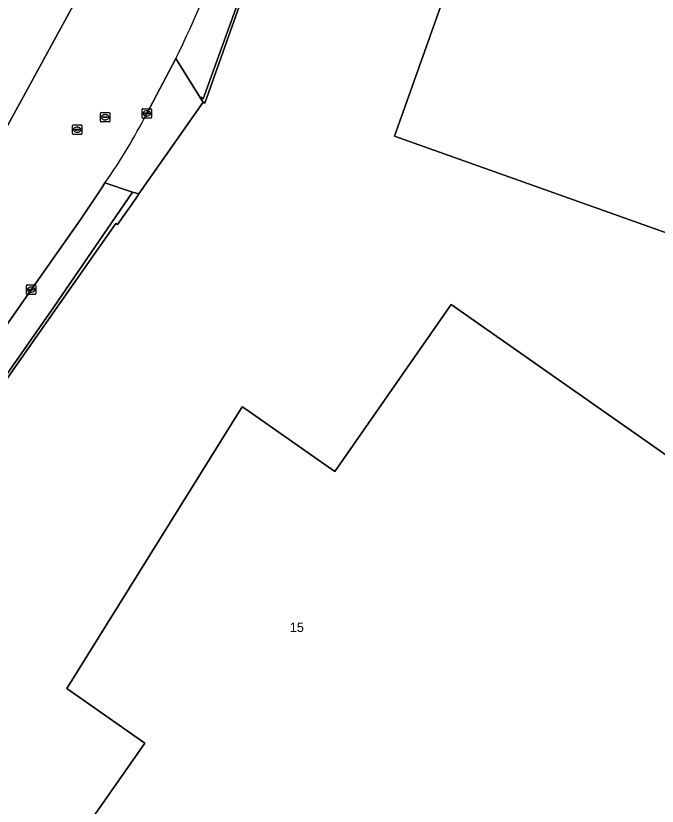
# Model space of a CAD drawing. Extents: x 155018 to 156648, y 383979 to 385733.
# Drawn here: x 155656.4 to 155724.8, y 384791.5 to 384875.8 of the extents above; entities that cross this region are included whole.
import ezdxf

# ---------------------------------------------------------------- set-up
doc = ezdxf.new("R2010")
doc.units = 0
for name, color, linetype in [('IMGEO_Erf', 7, 'Continuous'), ('IMGEO_Groenvoorziening', 7, 'Continuous'), ('IMGEO_Hek', 7, 'Continuous'), ('IMGEO_Kolk', 7, 'Continuous'), ('IMGEO_Pand', 7, 'Continuous'), ('IMGEO_Pand_nummerreeks', 7, 'Continuous'), ('IMGEO_Rijbaan_lokaal_gesloten', 7, 'Continuous'), ('IMGEO_Rijbaan_lokaal_open', 7, 'Continuous'), ('IMGEO_Rioolput', 7, 'Continuous'), ('IMGEO_Voetpad_open', 7, 'Continuous')]:
    doc.layers.add(name, color=color, linetype=linetype)

msp = doc.modelspace()

# ---------------------------------------------------------------- linework, layer by layer
at = {"layer": 'IMGEO_Erf'}
for points in [[(155819.22, 384821.585), (155773.299, 384837.894), (155771.729, 384833.45), (155765.854, 384835.53), (155767.438, 384839.985), (155767.038, 384840.129), (155766.348, 384838.189), (155696.765, 384862.93), (155727.468, 384949.235), (155728.915, 384948.717), (155740.174, 384980.395), (155746.303, 384997.642), (155748.837, 385004.772), (155747.33, 385005.279), (155749.138, 385010.33), (155750.623, 385009.797), (155753.183, 385017.001), (155762.359, 385042.817)], [(155730.975, 385018.536), (155724.402, 385000), (155719.139, 384985.171), (155718.598, 384983.687), (155716.009, 384976.585), (155715.7, 384975.738), (155702.844, 384939.771), (155702.172, 384937.868), (155696.786, 384922.628), (155696.12, 384920.743), (155684.958, 384889.381), (155684.425, 384889.57), (155682.806, 384885.06), (155682.424, 384883.902), (155681.972, 384882.563), (155681.138, 384880.234), (155681.15, 384879.519), (155676.547, 384866.454), (155676.35, 384866.575), (155669.497, 384856.797), (155669.212, 384856.331), (155667.198, 384853.508), (155667.02, 384853.625), (155588.106, 384741.158)], [(155662.832, 384787.785), (155670.123, 384798.196), (155661.809, 384804.018), (155680.521, 384834.071), (155680.893, 384833.825), (155690.4, 384827.184), (155702.826, 384844.99), (155791.889, 384782.576)]]:
    msp.add_lwpolyline(points, dxfattribs=at)
at = {"layer": 'IMGEO_Groenvoorziening'}
for points in [[(155681.15, 384879.519), (155681.138, 384880.234), (155676.369, 384866.915), (155676.09, 384867.098), (155676.052, 384866.993), (155676.35, 384866.575), (155676.547, 384866.454)], [(155667.02, 384853.625), (155667.198, 384853.508), (155669.212, 384856.331), (155669.497, 384856.797), (155668.817, 384856.954), (155660.389, 384844.659), (155636.862, 384811.074), (155608.808, 384771.107), (155594.019, 384750), (155586.655, 384739.49), (155582.342, 384733.152), (155582.316, 384732.95), (155582.416, 384732.885), (155582.631, 384733.19), (155586.789, 384739.087), (155588.217, 384741.112), (155588.106, 384741.158)]]:
    msp.add_lwpolyline(points, close=True, dxfattribs=at)
at = {"layer": 'IMGEO_Hek'}
for points in [[(155681.15, 384879.519), (155676.547, 384866.454), (155676.35, 384866.575)], [(155676.35, 384866.575), (155669.497, 384856.797)], [(155669.497, 384856.797), (155669.212, 384856.331)], [(155586.789, 384739.087), (155588.217, 384741.112), (155588.106, 384741.158), (155667.02, 384853.625), (155667.198, 384853.508), (155669.212, 384856.331)]]:
    msp.add_lwpolyline(points, dxfattribs=at)
at = {"layer": 'IMGEO_Kolk'}
for p, q in [((155669.836, 384864.948), (155669.836, 384865.8)), ((155669.911, 384865.874), (155670.763, 384865.874)), ((155670.837, 384865.8), (155670.837, 384864.948)), ((155670.095, 384865.368), (155670.095, 384865.38)), ((155670.533, 384865.331), (155670.135, 384865.331)), ((155670.138, 384865.417), (155670.536, 384865.417)), ((155670.347, 384865.094), (155670.322, 384865.094)), ((155670.324, 384865.654), (155670.349, 384865.654)), ((155670.579, 384865.38), (155670.579, 384865.368)), ((155670.763, 384864.874), (155669.911, 384864.874)), ((155657.498, 384846.145), (155657.498, 384846.997)), ((155657.573, 384847.071), (155658.425, 384847.071)), ((155657.757, 384846.565), (155657.757, 384846.577)), ((155658.195, 384846.528), (155657.797, 384846.528)), ((155657.8, 384846.614), (155658.198, 384846.614)), ((155657.986, 384846.851), (155658.011, 384846.851)), ((155658.241, 384846.577), (155658.241, 384846.565)), ((155658.499, 384846.997), (155658.499, 384846.145)), ((155658.425, 384846.071), (155657.573, 384846.071)), ((155658.009, 384846.291), (155657.984, 384846.291))]:
    msp.add_line(p, q, dxfattribs=at)
for points in [[(155669.836, 384864.948), (155669.836, 384865.8)], [(155669.911, 384865.874), (155670.763, 384865.874)], [(155670.837, 384865.8), (155670.837, 384864.948)], [(155670.763, 384864.874), (155669.911, 384864.874)], [(155657.498, 384846.145), (155657.498, 384846.997)], [(155657.573, 384847.071), (155658.425, 384847.071)], [(155658.499, 384846.997), (155658.499, 384846.145)], [(155658.425, 384846.071), (155657.573, 384846.071)]]:
    msp.add_lwpolyline(points, dxfattribs=at)
for centre, radius, start, end in [((155669.913, 384865.798), 0.0765, 91.55205, 178.44795), ((155669.913, 384865.798), 0.0765, 91.55205, 178.44795), ((155670.761, 384865.798), 0.0765, 1.55205, 88.44795), ((155670.761, 384865.798), 0.0765, 1.55205, 88.44795), ((155669.913, 384864.95), 0.0765, 181.55205, 268.44795), ((155669.913, 384864.95), 0.0765, 181.55205, 268.44795), ((155670.135, 384865.377), 0.0403, 85.87752, 175.75265), ((155670.132, 384865.367), 0.0366, 178.93798, 274.71019), ((155670.536, 384865.374), 0.043, 264.86636, 352.45326), ((155670.54, 384865.379), 0.0386, 1.73085, 96.63898), ((155670.761, 384864.95), 0.0765, 271.55205, 358.44795), ((155670.761, 384864.95), 0.0765, 271.55205, 358.44795), ((155657.575, 384846.995), 0.0765, 91.55205, 178.44795), ((155657.575, 384846.995), 0.0765, 91.55205, 178.44795), ((155657.797, 384846.574), 0.0403, 85.87752, 175.75265), ((155657.794, 384846.564), 0.0366, 178.93798, 274.71019), ((155658.198, 384846.571), 0.043, 264.86636, 352.45326), ((155658.202, 384846.576), 0.0386, 1.73085, 96.63898), ((155658.423, 384846.995), 0.0765, 1.55205, 88.44795), ((155658.423, 384846.995), 0.0765, 1.55205, 88.44795), ((155657.575, 384846.147), 0.0765, 181.55205, 268.44795), ((155657.575, 384846.147), 0.0765, 181.55205, 268.44795), ((155658.423, 384846.147), 0.0765, 271.55205, 358.44795), ((155658.423, 384846.147), 0.0765, 271.55205, 358.44795)]:
    msp.add_arc(centre, radius, start, end, dxfattribs=at)
for centre, major_axis, ratio, start_param, end_param in [((155670.323, 384865.374), (-0.387, 0.002), 0.722429, 4.712389, 7.853982), ((155670.348, 384865.374), (-0.39, 0.002), 0.717154, 1.570796, 4.712389), ((155657.985, 384846.571), (-0.387, 0.002), 0.722429, 4.712389, 7.853982), ((155658.01, 384846.571), (-0.39, 0.002), 0.717154, 1.570796, 4.712389)]:
    msp.add_ellipse(centre, major_axis=major_axis, ratio=ratio, start_param=start_param, end_param=end_param, dxfattribs=at)
at = {"layer": 'IMGEO_Pand'}
for points in [[(155828.255, 384911.336), (155796.179, 384922.734), (155808.139, 384956.274), (155787.494, 384963.57), (155797.027, 384990.446), (155809.649, 385026.028), (155762.359, 385042.817), (155753.183, 385017.001), (155750.623, 385009.797), (155749.138, 385010.33), (155747.33, 385005.279), (155748.837, 385004.772), (155746.303, 384997.642), (155740.174, 384980.395), (155728.915, 384948.717), (155727.468, 384949.235), (155696.765, 384862.93), (155766.348, 384838.189), (155767.038, 384840.129), (155767.438, 384839.985), (155765.854, 384835.53), (155771.729, 384833.45), (155773.299, 384837.894), (155819.22, 384821.585)], [(155791.889, 384782.576), (155702.826, 384844.99), (155690.4, 384827.184), (155680.893, 384833.825), (155680.521, 384834.071), (155661.809, 384804.018), (155670.123, 384798.196), (155662.832, 384787.785)]]:
    msp.add_lwpolyline(points, dxfattribs=at)
at = {"layer": 'IMGEO_Rijbaan_lokaal_gesloten'}
for points in [[(155654.873, 384862.94), (155662.924, 384877.712)], [(155662.924, 384877.712), (155654.873, 384862.94)], [(155670.338, 384865.374), (155673.443, 384871.217)], [(155557.839, 384704.064), (155557.967, 384704.242), (155558.339, 384703.973), (155565.165, 384713.55), (155573.586, 384725.999), (155578.096, 384732.463), (155583.356, 384740.042), (155586.289, 384744.214), (155590.343, 384750), (155608.173, 384775.45), (155620.847, 384793.568), (155634.39, 384812.919), (155647.778, 384831.987), (155658, 384846.57), (155663.285, 384854.104), (155665.547, 384857.446), (155665.874, 384857.967)]]:
    msp.add_lwpolyline(points, dxfattribs=at)
for centre, radius, start, end in [((155522.654, 384943.7), 167.306, 334.32678, 339.20632), ((155617.397, 384892.231), 59.364, 324.74661, 333.1009)]:
    msp.add_arc(centre, radius, start, end, dxfattribs=at)
at = {"layer": 'IMGEO_Rijbaan_lokaal_open'}
for points in [[(155676.35, 384866.575), (155676.052, 384866.993), (155673.443, 384871.217), (155670.338, 384865.374)], [(155665.874, 384857.967), (155668.817, 384856.954), (155669.497, 384856.797), (155676.35, 384866.575)]]:
    msp.add_lwpolyline(points, dxfattribs=at)
msp.add_arc((155617.397, 384892.231), 59.364, 324.74661, 333.1009, dxfattribs=at)
at = {"layer": 'IMGEO_Rioolput'}
for p, q in [((155665.382, 384864.54), (155665.382, 384865.392)), ((155665.457, 384865.466), (155666.309, 384865.466)), ((155665.641, 384864.96), (155665.641, 384864.972)), ((155665.684, 384865.009), (155666.082, 384865.009)), ((155665.87, 384865.246), (155665.895, 384865.246)), ((155666.125, 384864.972), (155666.125, 384864.96)), ((155666.383, 384865.392), (155666.383, 384864.54)), ((155662.497, 384864.139), (155663.349, 384864.139)), ((155666.309, 384864.466), (155665.457, 384864.466)), ((155666.079, 384864.923), (155665.681, 384864.923)), ((155665.893, 384864.686), (155665.868, 384864.686)), ((155662.422, 384863.213), (155662.422, 384864.065)), ((155662.681, 384863.633), (155662.681, 384863.645)), ((155663.119, 384863.596), (155662.721, 384863.596)), ((155662.724, 384863.682), (155663.122, 384863.682)), ((155662.933, 384863.359), (155662.908, 384863.359)), ((155662.91, 384863.919), (155662.935, 384863.919)), ((155663.165, 384863.645), (155663.165, 384863.633)), ((155663.423, 384864.065), (155663.423, 384863.213)), ((155663.349, 384863.139), (155662.497, 384863.139))]:
    msp.add_line(p, q, dxfattribs=at)
for points in [[(155665.382, 384864.54), (155665.382, 384865.392)], [(155665.457, 384865.466), (155666.309, 384865.466)], [(155666.383, 384865.392), (155666.383, 384864.54)], [(155662.497, 384864.139), (155663.349, 384864.139)], [(155666.309, 384864.466), (155665.457, 384864.466)], [(155662.422, 384863.213), (155662.422, 384864.065)], [(155663.423, 384864.065), (155663.423, 384863.213)], [(155663.349, 384863.139), (155662.497, 384863.139)]]:
    msp.add_lwpolyline(points, dxfattribs=at)
for centre, radius, start, end in [((155665.459, 384865.39), 0.0765, 91.55205, 178.44795), ((155665.459, 384865.39), 0.0765, 91.55205, 178.44795), ((155665.681, 384864.969), 0.0403, 85.87752, 175.75265), ((155665.678, 384864.959), 0.0366, 178.93798, 274.71019), ((155666.082, 384864.966), 0.043, 264.86636, 352.45326), ((155666.086, 384864.971), 0.0386, 1.73085, 96.63898), ((155666.307, 384865.39), 0.0765, 1.55205, 88.44795), ((155666.307, 384865.39), 0.0765, 1.55205, 88.44795), ((155662.499, 384864.063), 0.0765, 91.55205, 178.44795), ((155662.499, 384864.063), 0.0765, 91.55205, 178.44795), ((155663.347, 384864.063), 0.0765, 1.55205, 88.44795), ((155663.347, 384864.063), 0.0765, 1.55205, 88.44795), ((155665.459, 384864.542), 0.0765, 181.55205, 268.44795), ((155665.459, 384864.542), 0.0765, 181.55205, 268.44795), ((155666.307, 384864.542), 0.0765, 271.55205, 358.44795), ((155666.307, 384864.542), 0.0765, 271.55205, 358.44795), ((155662.721, 384863.642), 0.0403, 85.87752, 175.75265), ((155662.718, 384863.632), 0.0366, 178.93798, 274.71019), ((155663.122, 384863.639), 0.043, 264.86636, 352.45326), ((155663.126, 384863.644), 0.0386, 1.73085, 96.63898), ((155662.499, 384863.215), 0.0765, 181.55205, 268.44795), ((155662.499, 384863.215), 0.0765, 181.55205, 268.44795), ((155663.347, 384863.215), 0.0765, 271.55205, 358.44795), ((155663.347, 384863.215), 0.0765, 271.55205, 358.44795)]:
    msp.add_arc(centre, radius, start, end, dxfattribs=at)
for centre, major_axis, ratio, start_param, end_param in [((155665.869, 384864.966), (-0.387, 0.002), 0.722429, 4.712389, 7.853982), ((155665.894, 384864.966), (-0.39, 0.002), 0.717154, 1.570796, 4.712389), ((155662.909, 384863.639), (-0.387, 0.002), 0.722429, 4.712389, 7.853982), ((155662.934, 384863.639), (-0.39, 0.002), 0.717154, 1.570796, 4.712389)]:
    msp.add_ellipse(centre, major_axis=major_axis, ratio=ratio, start_param=start_param, end_param=end_param, dxfattribs=at)
at = {"layer": 'IMGEO_Voetpad_open'}
msp.add_lwpolyline([(155673.443, 384871.217), (155676.052, 384866.993), (155676.09, 384867.098), (155676.369, 384866.915), (155681.138, 384880.234), (155681.972, 384882.563), (155682.424, 384883.902), (155682.806, 384885.06), (155684.425, 384889.57), (155686.206, 384894.532), (155696.507, 384922.737), (155693.322, 384923.959), (155683.078, 384895.663), (155679.409, 384885.386), (155679.062, 384884.306)], dxfattribs=at)
msp.add_lwpolyline([(155586.655, 384739.49), (155594.019, 384750), (155608.808, 384771.107), (155636.862, 384811.074), (155660.389, 384844.659), (155668.817, 384856.954), (155665.874, 384857.967), (155665.547, 384857.446), (155663.285, 384854.104), (155658, 384846.57), (155647.778, 384831.987), (155634.39, 384812.919), (155620.847, 384793.568), (155608.173, 384775.45), (155590.343, 384750), (155586.289, 384744.214)], close=True, dxfattribs=at)
msp.add_arc((155522.654, 384943.7), 167.306, 334.32678, 339.20632, dxfattribs=at)

# ---------------------------------------------------------------- texts
at = {"layer": 'IMGEO_Pand_nummerreeks'}
msp.add_text('15', height=1, dxfattribs=at).set_placement((155685.603, 384810.064))

doc.saveas('drawing.dxf')
